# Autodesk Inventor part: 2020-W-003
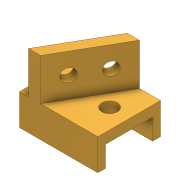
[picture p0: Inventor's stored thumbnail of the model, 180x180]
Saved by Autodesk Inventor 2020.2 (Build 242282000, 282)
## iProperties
Manager: www.cadconsulting.pl
Company: Fabian Stasiak CAD Consulting
Created: 2019-11
Part Number: 2020-W-003
Material: Mosiądz, miękki żółty
Document SubType Name: Modeling
Designer: F.Stasiak
Density: 8.47 g/cm^3
Appearance: Mosiądz — satynowy
Author: F.Stasiak
Subject: Zbiór ćwiczeń. Autodesk Inventor 2020. Kurs podstawowy
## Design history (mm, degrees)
node "Opisy"
  node "Wymiar liniowy 1" dims "d27" = 150 (derived)
  node "Wymiar liniowy 2" dims "d30" = 90 (derived)
  node "Wymiar liniowy 3" dims "d33" = 120 (derived)
  node "Wymiar liniowy 4" dims "d34" = 60 (derived)
  node "Wymiar średnicy 1" dims "d36" = 25 (derived)
  node "Wymiar średnicy 2" dims "d38" = 30 (derived)
  node "Wymiar liniowy 5" dims "d41" = 60 (derived)
  node "Wymiar kątowy 1" dims "d44" = 120 deg (derived)
  node "Wymiar liniowy 6" dims "d47" = 40 (derived)
  node "Wymiar liniowy 7" dims "d50" = 140 (derived)
  node "Wymiar liniowy 8" dims "d53" = 20 (derived)
  node "Wymiar liniowy 9" dims "d55" = 37.5 (derived)
  node "Wymiar liniowy 10" dims "d57" = 60 (derived)
sketch "Szkic1"
  geometry: L1 (-60, -60)-(60, -60); L2 (60, -60)-(60, 0); L3 (60, 0)-(-60, 0); L4 (-60, 0)-(-60, -60); L5 (-45, -60)-(-45, -20); L6 (-45, -20)-(45, -20); L7 (45, -20)-(45, -60); 3 further points
  constraints: 14 end point, 3 perpendicular, 2 midpoint, 2 parallel, 2 point on line, 1 coincident, 1 horizontal, 1 vertical, 1 vertical alignment
  dimensions: "d0" = 120 distance of L3.end L2.end; "d1" = 60 distance of L2.end L1.end; "d2" = 90 distance of L5.end L6.end; "d3" = 40 distance between parallel lines of L6 L1
extrude "Wyciągnięcie proste1" new body sketch "Szkic1" stored distance "d4" = 150; taper "d5" = 0 deg
sketch "Szkic2"
  geometry: L1 (0, 150)-(0, 0) reference; L2 (120, 150)-(120, 0) reference; L3 (0, 150)-(0, 0) reference; L4 (0, 132.735)-(120, 63.453); L5 (120, 0)-(120, 150) reference; L6 (120, 40.359)-(0, 109.641); 4 further points
  constraints: 4 end point, 4 point on line, 1 midpoint, 1 parallel
  dimensions: "d6" = 120 deg angle of L2 L6; "d7" = 20 distance between parallel lines of L4 L6
extrude "Wyciągnięcie proste2" join sketch "Szkic2" distance "d8" = 80; taper "d9" = 0 deg
sketch "Szkic3"
  geometry: L1 (-99.282, 40)-(-39.282, 40); L2 (-138.564, 0)-(-138.564, 80) reference; L3 (-138.564, 80)-(0, 80) reference; 4 further points
  constraints: 3 midpoint, 2 end point, 1 horizontal, 1 horizontal alignment, 1 vertical alignment
  dimensions: "d10" = 60 distance of L1.end L1.start
hole "Otwór1" sketch "Szkic3" at (-99.282, 40), (-39.282, 40) diameter "d11" = 25; stored, may be unused: countersink angle "d15" = 90 deg, drill point angle "d17" = 118 deg; dims "d12" = 6, "d13" = 4, "d14" = 2, "d16" = 8
sketch "Szkic5"
  geometry: L1 (60, 75)-(60, 0); L2 (15, 0)-(105, 0) reference; 2 further points
  constraints: 2 end point, 2 midpoint, 1 coincident
hole "Otwór2" sketch "Szkic5" at (60, 37.5) diameter "d18" = 30; stored, may be unused: countersink angle "d22" = 90 deg, drill point angle "d24" = 118 deg; dims "d19" = 6, "d20" = 4, "d21" = 2, "d23" = 8
node "Bryła1"
other parameters: "d25" = 0 (derived), "d28" = 6.87409 (derived), "d29" = 4.16263 (derived), "d31" = 0 (derived), "d35" = 19.20596 (derived), "d37" = 18.41701 (derived), "d39" = 0 (derived), "d42" = 1.87958 (derived), "d43" = 5.52313 (derived), "d45" = 0 (derived), "d48" = 4.52715 (derived), "d49" = 1.16108 (derived), "d51" = 0.55636 (derived), "d52" = 8.706 (derived), "d54" = 6.4878 (derived), "d56" = 5.48375 (derived)
